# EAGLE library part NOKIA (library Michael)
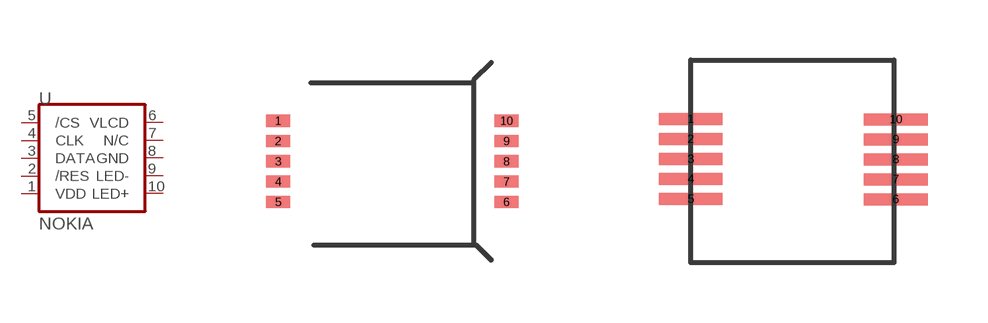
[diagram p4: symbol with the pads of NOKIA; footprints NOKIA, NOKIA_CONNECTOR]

Designator prefix -

## NOKIA1  [NOKIA]
1  VDD
2  /RES
3  DATA
4  CLK
5  /CS
6  VLCD
7  N/C
8  GND
9  LED-
10  LED+

## NOKIA2  [NOKIA_CONNECTOR]
Pads as for NOKIA

## NOKIA  [NOKIA_LCD]
Pads as for NOKIA

## Footprint NOKIA (pad centres in mm)
smd 0.61 x 0.305: 1 -2.603,1.905; 2 -2.603,1.397; 3 -2.603,0.889; 4 -2.603,0.381; 5 -2.603,-0.127; 6 3.111,-0.127; 7 3.111,0.381; 8 3.111,0.889; 9 3.111,1.397; 10 3.111,1.905

## Footprint NOKIA_CONNECTOR (pad centres in mm)
smd 1.6 x 0.3: 1 -2.415,1.131; 2 -2.415,0.631; 3 -2.415,0.131; 4 -2.415,-0.369; 5 -2.415,-0.869; 6 2.719,-0.877; 7 2.719,-0.377; 8 2.719,0.123; 9 2.719,0.623; 10 2.719,1.123

## Footprint NOKIA_LCD (pad centres in mm)
smd 0.61 x 0.305 rotated 135: 1 -10.8,-24.92; 2 -11.75,-25.18; 6 -1.93,-28.88; 7 -1.42,-28.15
smd 0.61 x 0.305: 3 -11.87,-26.79; 8 -1.13,-26.8
smd 0.61 x 0.305 rotated 225: 4 -11.59,-28.09; 5 -10.82,-28.67
smd 0.61 x 0.305 rotated 45: 9 -1.39,-25.42; 10 -1.97,-24.81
